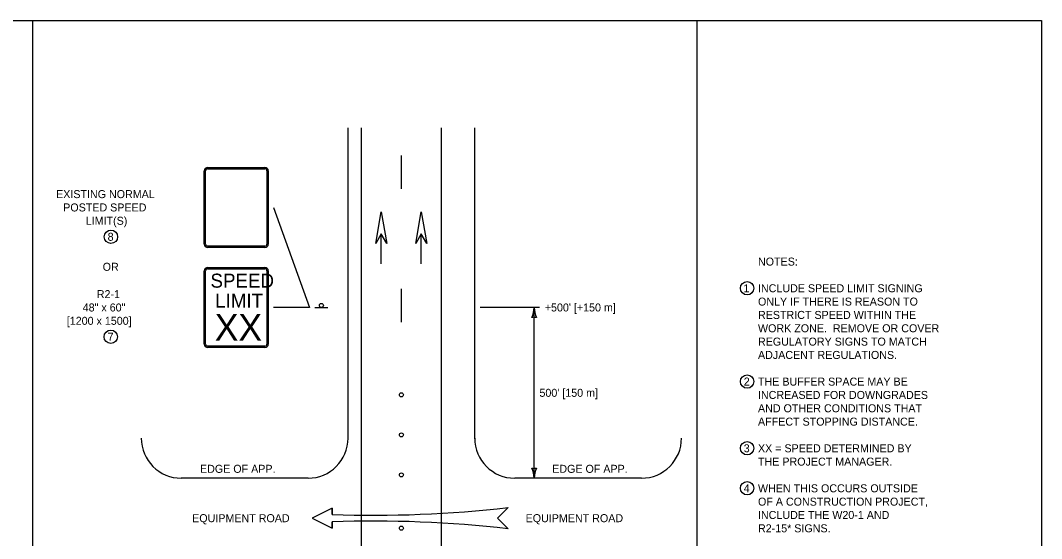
# Model space of a CAD drawing. Extents: x 49991.4 to 50021, y 49987.6 to 50011.4.
# Drawn here: x 50009.09 to 50016.75, y 49995.11 to 49999 of the extents above; entities that cross this region are included whole.
import ezdxf

# ---------------------------------------------------------------- set-up
doc = ezdxf.new("R2010")
doc.units = 0
for name, color, linetype in [('Level 1', 7, 'Continuous'), ('Level 2', 7, 'Continuous'), ('Level 3', 7, 'Continuous')]:
    doc.layers.add(name, color=color, linetype=linetype)

msp = doc.modelspace()

# ---------------------------------------------------------------- linework, layer by layer
at = {"layer": 'Level 1'}
for p, q in [((50011.5491, 49995.8668), (50011.5491, 49998.1941)), ((50011.6491, 49989.2068), (50011.6491, 49998.1941)), ((50012.2491, 49989.2068), (50012.2491, 49998.1941)), ((50012.4991, 49995.8624), (50012.4991, 49998.1941)), ((50011.9489, 49997.7359), (50011.9489, 49997.9859)), ((50010.4711, 49997.3218), (50010.4711, 49997.8718)), ((50010.4811, 49997.3218), (50010.4811, 49997.8718)), ((50010.4961, 49997.8968), (50010.9261, 49997.8968)), ((50010.4961, 49997.8868), (50010.9261, 49997.8868)), ((50010.9411, 49997.8718), (50010.9411, 49997.3218)), ((50010.9511, 49997.8718), (50010.9511, 49997.3218)), ((50011.7983, 49997.1734), (50011.7983, 49997.3993)), ((50011.7986, 49997.1734), (50011.7986, 49997.3993)), ((50012.098, 49997.1734), (50012.098, 49997.3993)), ((50012.0983, 49997.1734), (50012.0983, 49997.3993)), ((50010.9261, 49997.3068), (50010.4961, 49997.3068)), ((50010.9261, 49997.2968), (50010.4961, 49997.2968)), ((50010.4711, 49996.5718), (50010.4711, 49997.1218)), ((50010.4811, 49996.5718), (50010.4811, 49997.1218)), ((50010.4961, 49997.1468), (50010.9261, 49997.1468)), ((50010.4961, 49997.1368), (50010.9261, 49997.1368)), ((50010.9411, 49997.1218), (50010.9411, 49996.5718)), ((50010.9511, 49997.1218), (50010.9511, 49996.5718)), ((50011.9489, 49996.7359), (50011.9489, 49996.9859)), ((50011.3011, 49996.8468), (50011.3971, 49996.8468)), ((50010.9261, 49996.5568), (50010.4961, 49996.5568)), ((50010.9261, 49996.5468), (50010.4961, 49996.5468)), ((50011.2489, 49995.5668), (50010.2983, 49995.5668)), ((50013.7497, 49995.5668), (50012.7991, 49995.5668)), ((50011.4293, 49995.3418), (50011.2793, 49995.2668)), ((50011.4293, 49995.3418), (50011.2793, 49995.2668)), ((50011.4293, 49995.3418), (50011.4293, 49995.2943)), ((50011.4293, 49995.2943), (50011.4293, 49995.3418)), ((50012.7509, 49995.3468), (50012.6709, 49995.2668)), ((50012.6709, 49995.2668), (50012.7509, 49995.3468)), ((50011.2793, 49995.2668), (50011.4293, 49995.1918)), ((50011.2793, 49995.2668), (50011.4293, 49995.1918)), ((50012.6709, 49995.2668), (50012.7509, 49995.1868)), ((50012.7509, 49995.1868), (50012.6709, 49995.2668)), ((50011.4293, 49995.2393), (50011.4293, 49995.1918)), ((50011.4293, 49995.1918), (50011.4293, 49995.2393))]:
    msp.add_line(p, q, dxfattribs=at)
for points in [[(49999.3835, 49998.9992), (50016.7501, 49998.9992), (50016.7501, 49987.7988), (49999.3835, 49987.7988)], [(50011.7566, 49997.327), (50011.7983, 49997.5635), (50011.8402, 49997.327), (50011.7983, 49997.3992)], [(50012.0563, 49997.327), (50012.098, 49997.5635), (50012.1399, 49997.327), (50012.098, 49997.3992)]]:
    msp.add_lwpolyline(points, close=True, dxfattribs=at)
for centre, radius in [((50011.3491, 49996.862), 0.0152), ((50011.9491, 49996.1916), 0.015), ((50011.9491, 49995.8916), 0.015), ((50011.9491, 49995.5916), 0.015), ((50011.9491, 49995.1918), 0.015)]:
    msp.add_circle(centre, radius, dxfattribs=at)
for centre, radius, start, end in [((50010.4961, 49997.8718), 0.025, 90, 180), ((50010.4961, 49997.8718), 0.015, 90, 180), ((50010.9261, 49997.8718), 0.025, 0, 90), ((50010.9261, 49997.8718), 0.015, 0, 90), ((50010.4961, 49997.3218), 0.025, 180, 270), ((50010.4961, 49997.3218), 0.015, 180, 270), ((50010.9261, 49997.3218), 0.025, 270, 0), ((50010.9261, 49997.3218), 0.015, 270, 0), ((50010.4961, 49997.1218), 0.025, 90, 180), ((50010.4961, 49997.1218), 0.015, 90, 180), ((50010.9261, 49997.1218), 0.025, 0, 90), ((50010.9261, 49997.1218), 0.015, 0, 90), ((50010.4961, 49996.5718), 0.025, 180, 270), ((50010.4961, 49996.5718), 0.015, 180, 270), ((50010.9261, 49996.5718), 0.025, 270, 0), ((50010.9261, 49996.5718), 0.015, 270, 0), ((50010.2983, 49995.8668), 0.3, 180, 270), ((50011.2489, 49995.8668), 0.3, 270, 0), ((50012.7991, 49995.8668), 0.3, 180, 270), ((50013.7497, 49995.8668), 0.3, 270, 0), ((50011.7429, 50004.0608), 8.7721, 267.95127, 276.59844), ((50011.7429, 50004.0608), 8.7721, 267.95127, 276.59844), ((50011.7429, 49986.4728), 8.7721, 83.40156, 92.04873), ((50011.7429, 49986.4728), 8.7721, 83.40156, 92.04873)]:
    msp.add_arc(centre, radius, start, end, dxfattribs=at)
at = {"layer": 'Level 2'}
for centre in [(50009.7712, 49997.3768), (50014.5416, 49996.9912), (50009.7698, 49996.6268), (50014.5416, 49996.2912), (50014.5416, 49995.7912), (50014.5416, 49995.4912)]:
    msp.add_circle(centre, 0.05, dxfattribs=at)
at = {"layer": 'Level 3'}
for p, q in [((50009.1835, 49998.9992), (50009.1835, 49987.7988)), ((50014.1659, 49998.9992), (50014.1659, 49988.2257)), ((50010.9911, 49997.5968), (50011.2611, 49996.8468)), ((50011.2611, 49996.8468), (50010.9911, 49996.8468)), ((50012.9845, 49996.8468), (50012.5397, 49996.8468)), ((50012.9445, 49996.2068), (50012.9445, 49996.8468)), ((50012.9445, 49995.5668), (50012.9445, 49996.2068))]:
    msp.add_line(p, q, dxfattribs=at)
for centre, radius, start, end in [((50012.7118, 49996.8583), 0.233, 337.92284, 357.17269), ((50013.1667, 49996.856), 0.2223, 182.36048, 202.54399), ((50012.9445, 49996.7186), 0.0548, 72.13882, 107.86118), ((50012.7224, 49995.5576), 0.2223, 2.36048, 22.54399), ((50012.9445, 49995.695), 0.0548, 252.13882, 287.86118), ((50013.1773, 49995.5553), 0.233, 157.92284, 177.17269)]:
    msp.add_arc(centre, radius, start, end, dxfattribs=at)

# ---------------------------------------------------------------- texts
at = {"layer": 'Level 1'}
for s, height, p in [('SPEED', 0.10512, (50010.5173, 49996.9952)), ('LIMIT', 0.10512, (50010.5527, 49996.8451)), ('XX', 0.19892, (50010.5495, 49996.5978))]:
    msp.add_text(s, height=height, dxfattribs=at).set_placement(p)
at = {"layer": 'Level 2'}
for s, p in [('EXISTING NORMAL ', (50009.3595, 49997.6668)), ('POSTED SPEED ', (50009.413, 49997.5668)), ('LIMIT(S)', (50009.5819, 49997.4668)), ('8', (50009.7462, 49997.3468)), ('OR', (50009.709, 49997.1218)), ('NOTES:', (50014.6234, 49997.1608)), ('1', (50014.5144, 49996.9612)), ('INCLUDE SPEED LIMIT SIGNING', (50014.6234, 49996.9608)), ('R2-1', (50009.6649, 49996.9168)), ('48" x 60"', (50009.5593, 49996.8168)), ("+500' [+150 m]", (50013.0245, 49996.8168)), ('ONLY IF THERE IS REASON TO', (50014.6234, 49996.8608)), ('RESTRICT SPEED WITHIN THE', (50014.6234, 49996.7608)), ('[1200 x 1500]', (50009.4399, 49996.7168)), ('WORK ZONE.  REMOVE OR COVER', (50014.6234, 49996.6608)), ('7', (50009.746, 49996.5968)), ('REGULATORY SIGNS TO MATCH', (50014.6234, 49996.5608)), ('ADJACENT REGULATIONS.', (50014.6234, 49996.4608)), ('2', (50014.5167, 49996.2612)), ('THE BUFFER SPACE MAY BE', (50014.6234, 49996.2608)), ("500' [150 m]", (50012.9845, 49996.1768)), ('INCREASED FOR DOWNGRADES', (50014.6234, 49996.1608)), ('AND OTHER CONDITIONS THAT', (50014.6234, 49996.0608)), ('AFFECT STOPPING DISTANCE.', (50014.6234, 49995.9608)), ('3', (50014.5164, 49995.7608)), ('XX = SPEED DETERMINED BY', (50014.6234, 49995.7608)), ('THE PROJECT MANAGER.', (50014.6234, 49995.6608)), ('EDGE OF APP.', (50010.4389, 49995.6068)), ('EDGE OF APP.', (50013.0802, 49995.6068)), ('4', (50014.5167, 49995.4612)), ('WHEN THIS OCCURS OUTSIDE', (50014.6234, 49995.4608)), ('OF A CONSTRUCTION PROJECT,', (50014.6234, 49995.3608)), ('EQUIPMENT ROAD', (50010.38, 49995.2368)), ('EQUIPMENT ROAD', (50012.8808, 49995.2368)), ('INCLUDE THE W20-1 AND ', (50014.6234, 49995.2608)), ('R2-15* SIGNS.', (50014.6234, 49995.1608))]:
    msp.add_text(s, height=0.06, dxfattribs=at).set_placement(p)

doc.saveas('drawing.dxf')
